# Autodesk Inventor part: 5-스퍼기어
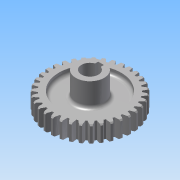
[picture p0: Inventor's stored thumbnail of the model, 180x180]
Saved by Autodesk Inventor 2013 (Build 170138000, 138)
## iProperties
Created: 2013-08
Part Number: 5-스퍼기어
Material: 강
Document SubType Name: Modeling
Designer: 한국산업디자인학원
Categories: <?xml version="1.0" encoding="UTF-16"?> <MemberInstance><Categories><FamilyTemplate><FamilyTemplateParameter ValueType="xs:double" Id="1" ObjectReferenceKey="da
Density: 1 g/cm^3
CustomPartVersion: 1
Author: 한국산업디자인학원
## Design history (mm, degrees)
sketch "Sketch1"
  geometry: C1 r 37 at (0, 0)
  constraints: 1 centre point
  dimensions: "d0" = 74 diameter of C1 (= da_da)
extrude "Extrusion1" new body sketch "Sketch1" distance "d1" = 15 (= da_b); taper "d2" = 0 deg
chamfer "모따기1" distance "d49" = 1; stored, may be unused: second distance "d50" = 2, angle "d51" = 45 deg
workplane "Work Plane2"
feature "피치 지름" dims "d4" = 10, "d5" = 0
workplane "Work Plane8"
workplane "Work Plane9"
sketch "스케치3"
  geometry: C1 r 36 at (0, 0) reference; C2 r 27.5 at (0, 0); C3 r 12.5 at (0, 0)
  constraints: 2 centre point, 2 coincident
  dimensions: "d52" = 55 diameter of C2; "d54" = 25 diameter of C3
extrude "돌출2" cut sketch "스케치3" distance "d55" = 5; taper "d56" = 0 deg
sketch "스케치4"
  geometry: C1 r 36 at (0, 0) reference; C2 r 27.5 at (0, 0); C3 r 12.5 at (0, 0)
  constraints: 2 centre point, 2 coincident
  dimensions: "d57" = 55 diameter of C2; "d59" = 25 diameter of C3
extrude "돌출3" cut sketch "스케치4" distance "d60" = 5; taper "d61" = 0 deg
node "작업 평면11"
sketch "스케치6"
  geometry: C1 r 12.5 at (0, 0) reference; 1 further point
extrude "돌출5" join sketch "스케치6" stored distance "d78" = 5; taper "d79" = 0 deg
hole "구멍2" diameter "d82" = 15; stored, may be unused: countersink angle "d86" = 90 deg, drill point angle "d88" = 118 deg; dims "d83" = 6, "d84" = 4, "d85" = 2, "d87" = 8, "d94" = 10, "d95" = 10
sketch "스케치8"
  geometry: L1 (-2.5, 9.8)-(2.5, 9.8); L2 (2.5, 9.8)-(2.5, 7.071); L3 (-2.5, 7.071)-(-2.5, 9.8); A1 r 7.5 centre (0, 0) between (2.5, 7.071) and (-2.5, 7.071) reference; A2 r 7.5 centre (0, 0) between (2.5, 7.071) and (-2.5, 7.071); 1 further point
  constraints: 6 end point, 6 point on circle, 1 centre point, 1 concentric, 1 horizontal, 1 midpoint, 1 parallel, 1 perpendicular, 1 vertical alignment
  dimensions: "d89" = 5 distance of L1.start L1.end; "d91" = 17.3 dimension on A1 L1
extrude "돌출6" cut sketch "스케치8" stored distance "d92" = 5; taper "d93" = 0 deg
feature "스퍼 기어" dims "da_b" = 15, "da_d" = 70, "da_aw" = 70, "da_da" = 74, "da_df" = 65, "da_dw" = 70, angle "da_beta" = 0 deg, "da_lefttooth" = 0, "da_righttooth" = 0
fillet "모깎기1" dims "d76" = 3
body "Solid1"
sketch "Sketch2"
  geometry: C1 r 37 at (0, 0) reference; C2 r 35 at (0, 0)
  constraints: 1 centre point, 1 coincident
  dimensions: "d3" = 70 diameter of C2 (= da_dw)
body "Srf1"
node "투영된 루프1"
other parameters: "d17" = 0, "d34" = 0.8976 (computed from da_z), "d39" = 0, "d41" = 0, "d47" = 0, "d48" = 0, "d77" = 31
